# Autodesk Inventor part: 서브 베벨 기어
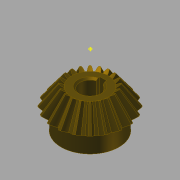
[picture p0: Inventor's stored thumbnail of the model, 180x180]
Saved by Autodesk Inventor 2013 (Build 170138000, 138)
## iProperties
Created: 2014-10
Part Number: 서브 베벨 기어
Material: 강철, 탄소
Document SubType Name: Modeling
Designer: KYOUNG IL JANG
Categories: <?xml version="1.0" encoding="UTF-16"?> <MemberInstance><Categories><FamilyTemplate><FamilyTemplateParameter ValueType="xs:double" Id="1" ObjectReferenceKey="da
Mass: 134.866 g
Surface Area: 63.6518 cm^2
Volume: 17.1585 cm^3
Density: 7.86 g/cm^3
CustomPartVersion: 1
Author: SeoGD™ [www.esajin.kr]
Revision Number: 1
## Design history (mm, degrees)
node "맨 위 점"
node "메쉬 평면2"
sketch "톱니 본체 스케치"
  geometry: L1 (0, 0)-(18.003, -31.331); L2 (18.003, -31.331)-(21.664, -28.891); L3 (21.664, -28.891)-(0, 0); L4 (20, -30)-(0, 0); L5 (10.813, -18.818)-(13.012, -17.352); L6 (18.003, -31.331)-(10.813, -18.818); L7 (21.664, -28.891)-(13.012, -17.352); L8 (0, -39.387)-(0, 6.564) reference; L9 (0, -30)-(21.664, -30)
  constraints: 16 end point, 4 point on line, 3 perpendicular, 2 collinear, 1 horizontal alignment, 1 vertical alignment
  dimensions: "d0" = 40 diameter of L4.start L8 (= da_de); "d1" = 36.00616 diameter of L1.end L8 (= da_dfe); "d2" = 43.3282 diameter of L2.end L8 (= da_dae); "d3" = 14.4 distance between parallel lines of L2 L5 (= da_b); "d4" = 28.8906 vertical distance of L2.end L1.start (= da_ve)
revolve "톱니 본체" sketch "톱니 본체 스케치" stored, may be unused: angle "d5" = 90 deg
node "시작점"
node "톱니 평면"
sketch "시작 스케치"
  geometry: L1 (0, -23.505)-(0, 10.645) reference; L2 (-0.834, -2.928)-(0.834, -2.928); A1 r 8.898 centre (-9.698, -3.713) between (-0.834, -2.928) and (-3.903, 3.04); A2 r 8.898 centre (9.698, -3.713) between (3.903, 3.04) and (0.834, -2.928); A3 r 27.357 centre (0, -24.037) between (3.903, 3.04) and (-3.903, 3.04); 1 further point
  constraints: 6 point on circle, 3 centre point, 3 symmetric about line, 2 end point, 1 coincident, 1 perpendicular, 1 other
  dimensions: "d7" = 8.89846 radius of A1 (= fd_rr); "d8" = 9.69794 horizontal distance of point (0, -24.037) A1.centre (= fd_x); "d9" = 20.32439 vertical distance of point (0, -24.037) A1.centre (= fd_y); "d57" = 27.35701 radius of A3 (= 0.5 x fd_dva + 0.3 x da_he); "d58" = 21.10901 distance from line of A3.centre L2 (= 0.5 x fd_dva - 1.12 x da_he)
node "끝점"
  node "끝 평면"
sketch "3D 스케치 오른쪽"
  node "Helical Curve Right" dims "d65" = 229.90621 (computed from da_dm, da_delta, da_beta), "d66" = 31.5, "d67" = 40 (= da_de), "d68" = -5.88003 (= -da_delta), "d69" = 12.16458 (computed from fd_loft, da_delta)
node "끝 평면 오른쪽"
sketch "끝 스케치 오른쪽"
  geometry: L1 (0, -22.649)-(0, 12.15) reference; L2 (-0.497, -1.72)-(0.497, -1.72); A1 r 5.299 centre (-5.775, -2.187) between (-0.497, -1.72) and (-2.324, 1.834); A2 r 5.299 centre (5.775, -2.187) between (2.324, 1.834) and (0.497, -1.72); A3 r 16.291 centre (0, -14.29) between (2.324, 1.834) and (-2.324, 1.834); 1 further point
  constraints: 6 point on circle, 3 centre point, 3 symmetric about line, 2 end point, 1 coincident, 1 perpendicular, 1 other
  dimensions: "d70" = 5.77526 horizontal distance of A3.centre A1.centre (computed from fd_x, fd_ratio); "d71" = 12.10346 vertical distance of point (0, -14.29) A1.centre (computed from fd_y, fd_ratio); "d72" = 5.29916 radius of A1 (computed from fd_rr, fd_ratio); "d73" = 12.57071 distance from line of point (0, -14.29) L2 (computed from d58, fd_ratio); "d74" = 16.29149 radius of A3 (computed from d57, fd_ratio)
feature "로프트 오른쪽" sketch "끝 스케치 오른쪽" dims "d75" = 0, "d77" = 0, "d79" = 0, "d80" = 90 deg, "d85" = 20, "d92" = 90 deg, "d93" = 90 deg, "da_teethtype" = 0 [user parameter]
sketch "3D 스케치 왼쪽"
  node "Helical Curve Left" dims "d26" = 229.90621 (computed from da_dm, da_delta, da_beta), "d27" = 12.16458 (computed from fd_loft, da_delta), "d28" = 40 (= da_de), "d29" = -5.88003 (= -da_delta)
node "끝 평면 왼쪽"
sketch "끝 스케치 왼쪽" dims "d56" = 10.82768 (derived)
  geometry: L1 (0, -35.087)-(0, 18.089) reference; L2 (-0.497, -1.716)-(0.497, -1.716); A1 r 5.299 centre (-5.775, -2.183) between (-0.497, -1.716) and (-2.324, 1.838); A2 r 5.299 centre (5.775, -2.183) between (2.324, 1.838) and (0.497, -1.716); A3 r 16.291 centre (0, -14.287) between (2.324, 1.838) and (-2.324, 1.838); 2 further points; 1 other entity
  constraints: 6 point on circle, 3 centre point, 3 symmetric about line, 2 end point, 1 coincident, 2 other
  dimensions: "d30" = 5.29916 radius of A1 (computed from fd_rr, fd_ratio); "d31" = 5.77526 horizontal distance of point (0, -14.287) A1.centre (computed from fd_x, fd_ratio); "d32" = 12.10346 vertical distance of A1.centre point (0, -14.287) (computed from fd_y, fd_ratio); "d61" = 16.29149 radius of A3 (computed from d57, fd_ratio); "d62" = 12.57071 distance from line of point (0, -14.287) L2 (computed from d58, fd_ratio)
feature "로프트 왼쪽" sketch "끝 스케치 왼쪽" dims "d35" = 0, "d37" = 0, "d39" = 0, "d40" = 90 deg, "d84" = 10, "d90" = 90 deg, "d91" = 90 deg, "da_teethtype" = 0 [user parameter]
sketch "본체 스케치"
  geometry: L1 (0, -35.038)-(0, -19.531) reference; L2 (18.003, -31.331)-(10.813, -18.818) reference; L3 (10.813, -18.818)-(0, -18.818); L4 (18.003, -31.331)-(0, -31.331)
  constraints: 4 end point, 2 perpendicular, 2 point on line
revolve "본체 고정" sketch "본체 스케치" stored, may be unused: angle "d46" = 90 deg
feature "피치 지름" dims angle "d47" = 90 deg
sketch "스케치8"
  geometry: C1 r 17 at (0, 0); 1 further point
  constraints: 1 centre point, 1 coincident
  dimensions: "d94" = 34 diameter of C1
extrude "돌출1" join sketch "스케치8" distance "d95" = 10; taper "d96" = 0 deg
sketch "스케치9"
  geometry: 1 further point
hole "구멍1" sketch "스케치9" at (0, 0) diameter "d97" = 12; stored, may be unused: countersink angle "d101" = 90 deg, drill point angle "d103" = 118 deg; dims "d98" = 6, "d99" = 4, "d100" = 2, "d102" = 8
sketch "스케치10"
  geometry: 1 further point
sketch "스케치11"
  geometry: 1 further point
sketch "스케치12"
  geometry: L1 (-2, 5.657)-(-2, 7.8); L2 (-2, 7.8)-(2, 7.8); L3 (2, 7.8)-(2, 5.657); A1 r 6 centre (0, 0) between (-2, 5.657) and (2, 5.657) reference; 1 further point
  constraints: 6 end point, 2 parallel, 2 point on circle, 1 perpendicular, 1 vertical
  dimensions: "d104" = 4 distance of L1.end L2.end; "d105" = 13.8 dimension on A1 L2
extrude "돌출2" cut sketch "스케치12" stored distance "d106" = 7; taper "d107" = 0 deg
chamfer "모따기1" distance "d108" = 1; stored, may be unused: second distance "d109" = 2, angle "d110" = 45 deg
body "Solid1"
feature "로프트" dims "d17" = 0, "d18" = 90 deg, "d19" = 0, "d20" = 90 deg, "d89" = 0, "da_teethtype" = 0 [user parameter]
pattern_circular "원형 패턴" dims angle "d22" = 360 deg, "d88" = 0, "da_teethtype" = 0 [user parameter]
pattern_circular "원형 패턴 오른쪽" dims angle "d82" = 360 deg, "da_teethtype" = 0 [user parameter]
pattern_circular "원형 패턴 왼쪽" dims angle "d42" = 360 deg, "da_teethtype" = 0 [user parameter]
sketch "끝 스케치"
  geometry: L1 (0, -15.359)-(0, 6.983) reference; L2 (-0.497, -1.72)-(0.497, -1.72); A1 r 5.299 centre (-5.775, -2.187) between (-0.497, -1.72) and (-2.324, 1.834); A2 r 5.299 centre (5.775, -2.187) between (2.324, 1.834) and (0.497, -1.72); A3 r 16.291 centre (0, -14.29) between (2.324, 1.834) and (-2.324, 1.834); 1 further point
  constraints: 6 point on circle, 3 centre point, 3 symmetric about line, 2 end point, 1 coincident, 1 other
  dimensions: "d12" = 5.29916 radius of A1 (computed from fd_rr, fd_ratio); "d15" = 5.77526 horizontal distance of A1.centre point (0, -14.29) (computed from fd_x, fd_ratio); "d16" = 12.10346 vertical distance of A1.centre point (0, -14.29) (computed from fd_y, fd_ratio); "d59" = 16.29149 radius of A3 (computed from d57, fd_ratio); "d60" = 12.57071 distance from line of A3.centre L2 (computed from d58, fd_ratio)
sketch "Sketch6"
  geometry: L1 (20, -30)-(0, 0) reference; L2 (0, -37.8)-(0, 6.3) reference
body "Srf1"
other parameters: "da_b" = 14.4 [user parameter; used in 2 equation terms], "da_de" = 40 [user parameter; used in 4 equation terms], "da_dae" = 43.3282 [user parameter; used in 2 equation terms], "da_dfe" = 36.00616 [user parameter; used in 1 equation term], "da_le" = 36.05551 [user parameter; used in 1 equation term], "da_omega" = 90 deg [user parameter; used in 1 equation term], "da_beta" = 0 [user parameter; used in 2 equation terms], "da_delta" = 5.88003 [user parameter; used in 8 equation terms], "da_alpha" = 20 deg [user parameter; used in 2 equation terms], "da_he" = 4.4 [user parameter; used in 4 equation terms], "da_ve" = 28.8906 [user parameter; used in 1 equation term], "fd_dv" = 48.07402 (computed from da_de, da_delta) [user parameter; used in 1 equation term], "fd_dva" = 52.07402 (computed from da_dae, da_delta) [user parameter; used in 3 equation terms], "fd_dvb" = 45.1748 (computed from fd_dv, da_alpha) [user parameter; used in 2 equation terms], "da_zv" = 240.37008 [user parameter; used in 1 equation term], "fd_loft" = 14.62 (= da_b + 0.05 x da_he) [user parameter; used in 4 equation terms], "fd_ratio" = 5.95514 (computed from da_le, fd_loft) [user parameter; used in 15 equation terms], "fd_rr" = 8.89846 (computed from fd_dd, fd_dvb) [user parameter; used in 6 equation terms], "fd_angle" = 0.66075 (computed from da_zv) [user parameter; used in 4 equation terms], "fd_x1" = 1.58709 (computed from da_dvw, fd_angle) [user parameter; used in 1 equation term], "fd_y1" = 23.98456 (computed from da_dvw, fd_angle) [user parameter; used in 1 equation term], "fd_x2" = 8.11084 (computed from fd_rr, fd_angle2, fd_angle) [user parameter; used in 1 equation term], "fd_y2" = 3.66016 (computed from fd_rr, fd_angle2, fd_angle) [user parameter; used in 1 equation term], "fd_x" = 9.69794 (= fd_x1 + fd_x2) [user parameter; used in 4 equation terms], "fd_y" = 20.32439 (= fd_y1 - fd_y2) [user parameter; used in 4 equation terms], "fd_angle2" = 3.57832 (computed from fd_dvb, fd_dd, da_alpha) [user parameter; used in 2 equation terms], "fd_dd" = 48.55402 (= fd_dva - 0.8 x da_he) [user parameter; used in 2 equation terms], "da_dvw" = 48.07402 [user parameter; used in 2 equation terms], "d11" = 14.62 (= fd_loft), "da_dm" = 32.01232 [user parameter; used in 2 equation terms], "da_x" = 0 [user parameter], "da_m" = 2 [user parameter], "d48" = 0, "d49" = 0, "d50" = 90 deg (= da_omega), "d51" = 9 deg (computed from da_z), "d52" = 0, "d53" = 0, "d54" = 0
